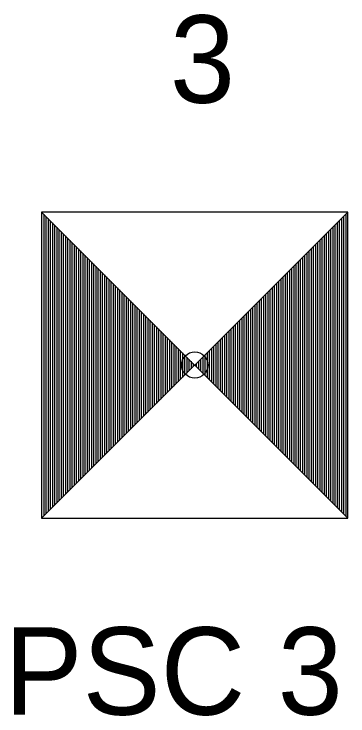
# Model space of a CAD drawing. Extents: x 1529475 to 1532053, y 876698 to 877911.
# Drawn here: x 1530016.17 to 1530019.99, y 877417.94 to 877425.97 of the extents above; entities that cross this region are included whole.
import ezdxf

# ---------------------------------------------------------------- set-up
doc = ezdxf.new("R2010")
doc.units = 0
for name, color, linetype in [('RD_HC_Survey', 7, 'Continuous'), ('RD_HC_txCode', 7, 'Continuous'), ('RD_SMD_Locator', 7, 'Continuous')]:
    doc.layers.add(name, color=color, linetype=linetype)

msp = doc.modelspace()

# ---------------------------------------------------------------- linework, layer by layer
at = {"layer": 'RD_HC_Survey'}
for p, q in [((1530016.4872, 877423.7038), (1530019.9872, 877420.2038)), ((1530019.9872, 877423.7038), (1530016.4872, 877420.2038)), ((1530016.512, 877423.679), (1530016.512, 877420.2286)), ((1530019.9624, 877423.679), (1530019.9624, 877420.2286)), ((1530016.5367, 877423.6543), (1530016.5367, 877420.2533)), ((1530016.5615, 877423.6295), (1530016.5615, 877420.2781)), ((1530016.5862, 877423.6048), (1530016.5862, 877420.3028)), ((1530019.8882, 877423.6048), (1530019.8882, 877420.3028)), ((1530019.9129, 877423.6295), (1530019.9129, 877420.2781)), ((1530019.9377, 877423.6543), (1530019.9377, 877420.2533)), ((1530016.611, 877423.58), (1530016.611, 877420.3276)), ((1530016.6357, 877423.5553), (1530016.6357, 877420.3523)), ((1530016.6604, 877423.5306), (1530016.6604, 877420.377)), ((1530019.814, 877423.5306), (1530019.814, 877420.377)), ((1530019.8387, 877423.5553), (1530019.8387, 877420.3523)), ((1530019.8634, 877423.58), (1530019.8634, 877420.3276)), ((1530016.6852, 877423.5058), (1530016.6852, 877420.4018)), ((1530016.7099, 877423.4811), (1530016.7099, 877420.4265)), ((1530016.7347, 877423.4563), (1530016.7347, 877420.4513)), ((1530019.7397, 877423.4563), (1530019.7397, 877420.4513)), ((1530019.7645, 877423.4811), (1530019.7645, 877420.4265)), ((1530019.7892, 877423.5058), (1530019.7892, 877420.4018)), ((1530016.7594, 877423.4316), (1530016.7594, 877420.476)), ((1530016.7842, 877423.4068), (1530016.7842, 877420.5008)), ((1530016.8089, 877423.3821), (1530016.8089, 877420.5255)), ((1530016.8337, 877423.3573), (1530016.8337, 877420.5503)), ((1530019.6407, 877423.3573), (1530019.6407, 877420.5503)), ((1530019.6655, 877423.3821), (1530019.6655, 877420.5255)), ((1530019.6902, 877423.4068), (1530019.6902, 877420.5008)), ((1530019.715, 877423.4316), (1530019.715, 877420.476)), ((1530016.8584, 877423.3326), (1530016.8584, 877420.575)), ((1530016.8832, 877423.3078), (1530016.8832, 877420.5998)), ((1530016.9079, 877423.2831), (1530016.9079, 877420.6245)), ((1530019.5665, 877423.2831), (1530019.5665, 877420.6245)), ((1530019.5912, 877423.3078), (1530019.5912, 877420.5998)), ((1530019.616, 877423.3326), (1530019.616, 877420.575)), ((1530016.9327, 877423.2583), (1530016.9327, 877420.6493)), ((1530016.9574, 877423.2336), (1530016.9574, 877420.674)), ((1530016.9822, 877423.2088), (1530016.9822, 877420.6988)), ((1530019.4922, 877423.2088), (1530019.4922, 877420.6988)), ((1530019.517, 877423.2336), (1530019.517, 877420.674)), ((1530019.5417, 877423.2583), (1530019.5417, 877420.6493)), ((1530017.0069, 877423.1841), (1530017.0069, 877420.7235)), ((1530017.0317, 877423.1593), (1530017.0317, 877420.7483)), ((1530017.0564, 877423.1346), (1530017.0564, 877420.773)), ((1530019.418, 877423.1346), (1530019.418, 877420.773)), ((1530019.4427, 877423.1593), (1530019.4427, 877420.7483)), ((1530019.4675, 877423.1841), (1530019.4675, 877420.7235)), ((1530017.0812, 877423.1098), (1530017.0812, 877420.7978)), ((1530017.1059, 877423.0851), (1530017.1059, 877420.8225)), ((1530017.1307, 877423.0603), (1530017.1307, 877420.8473)), ((1530017.1554, 877423.0356), (1530017.1554, 877420.872)), ((1530019.319, 877423.0356), (1530019.319, 877420.872)), ((1530019.3437, 877423.0603), (1530019.3437, 877420.8473)), ((1530019.3685, 877423.0851), (1530019.3685, 877420.8225)), ((1530019.3932, 877423.1098), (1530019.3932, 877420.7978)), ((1530017.1802, 877423.0108), (1530017.1802, 877420.8968)), ((1530017.2049, 877422.9861), (1530017.2049, 877420.9215)), ((1530017.2297, 877422.9613), (1530017.2297, 877420.9463)), ((1530019.2447, 877422.9613), (1530019.2447, 877420.9463)), ((1530019.2695, 877422.9861), (1530019.2695, 877420.9215)), ((1530019.2942, 877423.0108), (1530019.2942, 877420.8968)), ((1530017.2544, 877422.9366), (1530017.2544, 877420.971)), ((1530017.2792, 877422.9118), (1530017.2792, 877420.9958)), ((1530017.3039, 877422.8871), (1530017.3039, 877421.0205)), ((1530019.1705, 877422.8871), (1530019.1705, 877421.0205)), ((1530019.1952, 877422.9118), (1530019.1952, 877420.9958)), ((1530019.22, 877422.9366), (1530019.22, 877420.971)), ((1530017.3287, 877422.8623), (1530017.3287, 877421.0453)), ((1530017.3534, 877422.8376), (1530017.3534, 877421.07)), ((1530017.3782, 877422.8128), (1530017.3782, 877421.0948)), ((1530019.0962, 877422.8128), (1530019.0962, 877421.0948)), ((1530019.121, 877422.8376), (1530019.121, 877421.07)), ((1530019.1457, 877422.8623), (1530019.1457, 877421.0453)), ((1530017.4029, 877422.7881), (1530017.4029, 877421.1195)), ((1530017.4277, 877422.7633), (1530017.4277, 877421.1443)), ((1530017.4524, 877422.7386), (1530017.4524, 877421.169)), ((1530017.4772, 877422.7138), (1530017.4772, 877421.1938)), ((1530018.9972, 877422.7138), (1530018.9972, 877421.1938)), ((1530019.022, 877422.7386), (1530019.022, 877421.169)), ((1530019.0467, 877422.7633), (1530019.0467, 877421.1443)), ((1530019.0715, 877422.7881), (1530019.0715, 877421.1195)), ((1530017.5019, 877422.6891), (1530017.5019, 877421.2185)), ((1530017.5267, 877422.6643), (1530017.5267, 877421.2433)), ((1530017.5514, 877422.6396), (1530017.5514, 877421.268)), ((1530018.923, 877422.6396), (1530018.923, 877421.268)), ((1530018.9477, 877422.6643), (1530018.9477, 877421.2433)), ((1530018.9725, 877422.6891), (1530018.9725, 877421.2185)), ((1530017.5761, 877422.6149), (1530017.5761, 877421.2927)), ((1530017.6009, 877422.5901), (1530017.6009, 877421.3175)), ((1530017.6256, 877422.5654), (1530017.6256, 877421.3422)), ((1530018.8488, 877422.5654), (1530018.8488, 877421.3422)), ((1530018.8735, 877422.5901), (1530018.8735, 877421.3175)), ((1530018.8983, 877422.6149), (1530018.8983, 877421.2927)), ((1530017.6504, 877422.5406), (1530017.6504, 877421.367)), ((1530017.6751, 877422.5159), (1530017.6751, 877421.3917)), ((1530017.6999, 877422.4911), (1530017.6999, 877421.4165)), ((1530018.7745, 877422.4911), (1530018.7745, 877421.4165)), ((1530018.7993, 877422.5159), (1530018.7993, 877421.3917)), ((1530018.824, 877422.5406), (1530018.824, 877421.367)), ((1530017.7246, 877422.4664), (1530017.7246, 877421.4412)), ((1530017.7494, 877422.4416), (1530017.7494, 877421.466)), ((1530017.7741, 877422.4169), (1530017.7741, 877421.4907)), ((1530017.7989, 877422.3921), (1530017.7989, 877421.5155)), ((1530018.6755, 877422.3921), (1530018.6755, 877421.5155)), ((1530018.7003, 877422.4169), (1530018.7003, 877421.4907)), ((1530018.725, 877422.4416), (1530018.725, 877421.466)), ((1530018.7498, 877422.4664), (1530018.7498, 877421.4412)), ((1530017.8236, 877422.3674), (1530017.8236, 877421.5402)), ((1530017.8484, 877422.3426), (1530017.8484, 877421.565)), ((1530017.8731, 877422.3179), (1530017.8731, 877421.5897)), ((1530018.6013, 877422.3179), (1530018.6013, 877421.5897)), ((1530018.626, 877422.3426), (1530018.626, 877421.565)), ((1530018.6508, 877422.3674), (1530018.6508, 877421.5402)), ((1530017.8979, 877422.2931), (1530017.8979, 877421.6145)), ((1530017.9226, 877422.2684), (1530017.9226, 877421.6392)), ((1530017.9474, 877422.2436), (1530017.9474, 877421.664)), ((1530018.527, 877422.2436), (1530018.527, 877421.664)), ((1530018.5518, 877422.2684), (1530018.5518, 877421.6392)), ((1530018.5765, 877422.2931), (1530018.5765, 877421.6145)), ((1530017.9721, 877422.2189), (1530017.9721, 877421.6887)), ((1530017.9969, 877422.1941), (1530017.9969, 877421.7135)), ((1530018.0216, 877422.1694), (1530018.0216, 877421.7382)), ((1530018.4528, 877422.1694), (1530018.4528, 877421.7382)), ((1530018.4775, 877422.1941), (1530018.4775, 877421.7135)), ((1530018.5023, 877422.2189), (1530018.5023, 877421.6887)), ((1530018.0464, 877422.1446), (1530018.0464, 877421.763)), ((1530018.0711, 877422.1199), (1530018.0711, 877421.7877)), ((1530018.0959, 877422.0951), (1530018.0959, 877421.8125)), ((1530018.1206, 877422.0704), (1530018.1206, 877421.8372)), ((1530018.3538, 877422.0704), (1530018.3538, 877421.8372)), ((1530018.3785, 877422.0951), (1530018.3785, 877421.8125)), ((1530018.4033, 877422.1199), (1530018.4033, 877421.7877)), ((1530018.428, 877422.1446), (1530018.428, 877421.763)), ((1530018.1454, 877422.0456), (1530018.1454, 877421.862)), ((1530018.1701, 877422.0209), (1530018.1701, 877421.8867)), ((1530018.1949, 877421.9961), (1530018.1949, 877421.9115)), ((1530018.2795, 877421.9961), (1530018.2795, 877421.9115)), ((1530018.3043, 877422.0209), (1530018.3043, 877421.8867)), ((1530018.329, 877422.0456), (1530018.329, 877421.862)), ((1530018.2196, 877421.9714), (1530018.2196, 877421.9362)), ((1530018.2548, 877421.9714), (1530018.2548, 877421.9362))]:
    msp.add_line(p, q, dxfattribs=at)
msp.add_lwpolyline([(1530019.9872, 877423.7038), (1530016.4872, 877423.7038), (1530016.4872, 877420.2038), (1530019.9872, 877420.2038)], close=True, dxfattribs=at)
at = {"layer": 'RD_SMD_Locator'}
msp.add_circle((1530018.2372, 877421.9538), 0.15, dxfattribs=at)

# ---------------------------------------------------------------- texts
at = {"layer": 'RD_HC_txCode'}
for s, p in [('3', (1530017.9537, 877424.9538)), ('PSC 3', (1530016.064, 877417.9538))]:
    msp.add_text(s, height=1, dxfattribs=at).set_placement(p)

doc.saveas('drawing.dxf')
